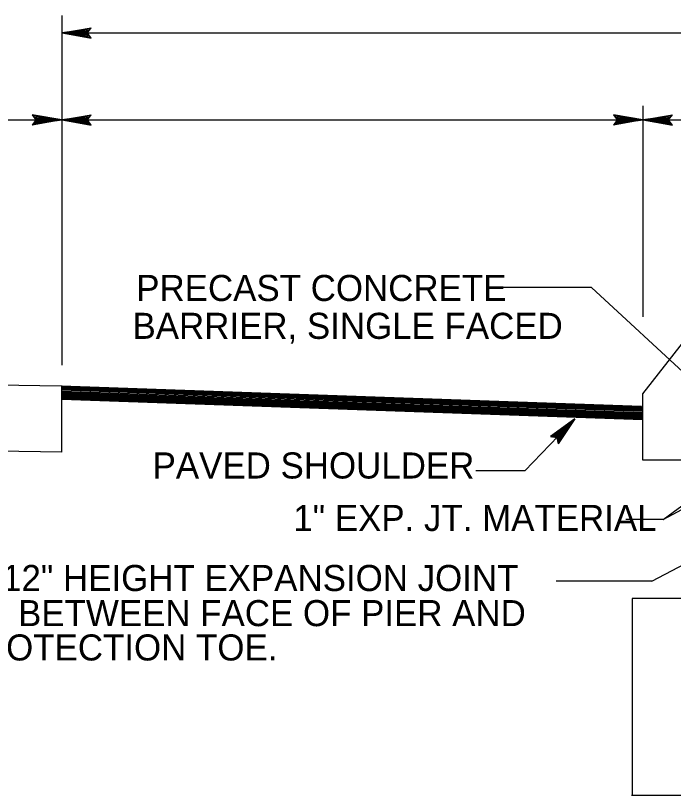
# Model space of a CAD drawing. Extents: x 1553195 to 1553792, y 810516 to 810787.
# Drawn here: x 1553752.03 to 1553765.27, y 810725.5 to 810741.19 of the extents above; entities that cross this region are included whole.
import ezdxf

# ---------------------------------------------------------------- set-up
doc = ezdxf.new("R2010")
doc.units = 0
doc.layers.add('Old_Level_28', color=7, linetype='Continuous')

msp = doc.modelspace()

# ---------------------------------------------------------------- linework, layer by layer
at = {"layer": 'Old_Level_28'}
for p, q in [((1553752.957, 810741.194), (1553752.957, 810734.157)), ((1553752.957, 810740.846), (1553753.552, 810740.948)), ((1553752.957, 810740.846), (1553753.539, 810740.933)), ((1553753.53, 810740.92), (1553752.957, 810740.846)), ((1553752.957, 810740.846), (1553753.519, 810740.904)), ((1553753.477, 810740.846), (1553753.552, 810740.948)), ((1553753.508, 810740.888), (1553752.957, 810740.846)), ((1553752.957, 810740.846), (1553753.497, 810740.875)), ((1553753.486, 810740.859), (1553752.957, 810740.846)), ((1553752.957, 810740.846), (1553767.332, 810740.846)), ((1553752.957, 810740.846), (1553753.552, 810740.739)), ((1553753.539, 810740.754), (1553752.957, 810740.846)), ((1553752.957, 810740.846), (1553753.53, 810740.768)), ((1553753.519, 810740.784), (1553752.957, 810740.846)), ((1553752.957, 810740.846), (1553753.508, 810740.799)), ((1553753.497, 810740.813), (1553752.957, 810740.846)), ((1553752.957, 810740.846), (1553753.486, 810740.828)), ((1553753.477, 810740.846), (1553752.957, 810740.846)), ((1553753.552, 810740.739), (1553753.477, 810740.846)), ((1553764.653, 810739.379), (1553764.653, 810735.13)), ((1553752.957, 810739.095), (1553752.363, 810739.197)), ((1553752.363, 810739.197), (1553752.439, 810739.095)), ((1553752.373, 810739.181), (1553752.957, 810739.095)), ((1553752.957, 810739.095), (1553753.552, 810739.197)), ((1553752.957, 810739.095), (1553753.539, 810739.181)), ((1553753.477, 810739.095), (1553753.552, 810739.197)), ((1553764.653, 810739.095), (1553764.059, 810739.197)), ((1553764.059, 810739.197), (1553764.135, 810739.095)), ((1553764.068, 810739.181), (1553764.653, 810739.095)), ((1553764.653, 810739.095), (1553765.248, 810739.197)), ((1553764.653, 810739.095), (1553765.234, 810739.181)), ((1553765.172, 810739.095), (1553765.248, 810739.197)), ((1553746.957, 810739.095), (1553752.957, 810739.095)), ((1553752.957, 810739.095), (1553752.363, 810738.988)), ((1553752.439, 810739.095), (1553752.363, 810738.988)), ((1553752.957, 810739.095), (1553752.373, 810739.004)), ((1553752.957, 810739.095), (1553752.383, 810739.168)), ((1553752.383, 810739.017), (1553752.957, 810739.095)), ((1553752.397, 810739.152), (1553752.957, 810739.095)), ((1553752.957, 810739.095), (1553752.397, 810739.032)), ((1553752.957, 810739.095), (1553752.406, 810739.137)), ((1553752.406, 810739.048), (1553752.957, 810739.095)), ((1553752.419, 810739.123), (1553752.957, 810739.095)), ((1553752.957, 810739.095), (1553752.419, 810739.061)), ((1553752.957, 810739.095), (1553752.43, 810739.108)), ((1553752.43, 810739.077), (1553752.957, 810739.095)), ((1553752.439, 810739.095), (1553752.957, 810739.095)), ((1553753.53, 810739.168), (1553752.957, 810739.095)), ((1553752.957, 810739.095), (1553753.519, 810739.152)), ((1553753.508, 810739.137), (1553752.957, 810739.095)), ((1553752.957, 810739.095), (1553753.497, 810739.123)), ((1553753.486, 810739.108), (1553752.957, 810739.095)), ((1553752.957, 810739.095), (1553764.653, 810739.095)), ((1553752.957, 810739.095), (1553753.552, 810738.988)), ((1553753.539, 810739.004), (1553752.957, 810739.095)), ((1553752.957, 810739.095), (1553753.53, 810739.017)), ((1553753.519, 810739.032), (1553752.957, 810739.095)), ((1553752.957, 810739.095), (1553753.508, 810739.048)), ((1553753.497, 810739.061), (1553752.957, 810739.095)), ((1553752.957, 810739.095), (1553753.486, 810739.077)), ((1553753.477, 810739.095), (1553752.957, 810739.095)), ((1553753.552, 810738.988), (1553753.477, 810739.095)), ((1553764.653, 810739.095), (1553764.059, 810738.988)), ((1553764.135, 810739.095), (1553764.059, 810738.988)), ((1553764.653, 810739.095), (1553764.068, 810739.004)), ((1553764.653, 810739.095), (1553764.079, 810739.168)), ((1553764.079, 810739.017), (1553764.653, 810739.095)), ((1553764.093, 810739.152), (1553764.653, 810739.095)), ((1553764.653, 810739.095), (1553764.093, 810739.032)), ((1553764.653, 810739.095), (1553764.101, 810739.137)), ((1553764.101, 810739.048), (1553764.653, 810739.095)), ((1553764.115, 810739.123), (1553764.653, 810739.095)), ((1553764.653, 810739.095), (1553764.115, 810739.061)), ((1553764.653, 810739.095), (1553764.126, 810739.108)), ((1553764.126, 810739.077), (1553764.653, 810739.095)), ((1553764.135, 810739.095), (1553764.653, 810739.095)), ((1553765.226, 810739.168), (1553764.653, 810739.095)), ((1553764.653, 810739.095), (1553765.214, 810739.152)), ((1553765.204, 810739.137), (1553764.653, 810739.095)), ((1553764.653, 810739.095), (1553765.192, 810739.123)), ((1553765.181, 810739.108), (1553764.653, 810739.095)), ((1553764.653, 810739.095), (1553765.248, 810738.988)), ((1553765.234, 810739.004), (1553764.653, 810739.095)), ((1553764.653, 810739.095), (1553765.226, 810739.017)), ((1553765.214, 810739.032), (1553764.653, 810739.095)), ((1553764.653, 810739.095), (1553765.204, 810739.048)), ((1553765.192, 810739.061), (1553764.653, 810739.095)), ((1553764.653, 810739.095), (1553765.181, 810739.077)), ((1553765.172, 810739.095), (1553764.653, 810739.095)), ((1553764.653, 810739.095), (1553767.332, 810739.095)), ((1553765.248, 810738.988), (1553765.172, 810739.095)), ((1553763.619, 810735.72), (1553761.693, 810735.72)), ((1553763.619, 810735.72), (1553765.799, 810733.706)), ((1553764.653, 810733.581), (1553765.477, 810734.634)), ((1553746.957, 810733.85), (1553752.95, 810733.739)), ((1553752.95, 810733.739), (1553764.626, 810733.33)), ((1553752.957, 810732.408), (1553752.957, 810733.748)), ((1553752.957, 810733.731), (1553764.65, 810733.321)), ((1553752.957, 810733.717), (1553764.65, 810733.311)), ((1553752.957, 810733.702), (1553764.65, 810733.295)), ((1553752.957, 810733.688), (1553764.65, 810733.281)), ((1553752.957, 810733.672), (1553764.65, 810733.263)), ((1553752.957, 810733.659), (1553764.65, 810733.248)), ((1553752.957, 810733.637), (1553764.65, 810733.23)), ((1553752.957, 810733.617), (1553764.65, 810733.208)), ((1553752.957, 810733.597), (1553764.65, 810733.19)), ((1553752.957, 810733.577), (1553764.65, 810733.168)), ((1553752.957, 810733.561), (1553764.65, 810733.152)), ((1553752.957, 810733.542), (1553764.65, 810733.13)), ((1553752.957, 810733.523), (1553764.65, 810733.115)), ((1553764.653, 810732.243), (1553764.653, 810733.581)), ((1553752.957, 810733.513), (1553764.65, 810733.103)), ((1553752.957, 810733.499), (1553764.65, 810733.09)), ((1553752.957, 810733.488), (1553764.65, 810733.077)), ((1553752.957, 810733.477), (1553764.65, 810733.07)), ((1553752.957, 810733.47), (1553764.65, 810733.061)), ((1553762.276, 810732.033), (1553763.287, 810733.075)), ((1553763.287, 810733.075), (1553762.796, 810732.722)), ((1553762.816, 810732.718), (1553763.287, 810733.075)), ((1553763.287, 810733.075), (1553762.834, 810732.716)), ((1553762.85, 810732.713), (1553763.287, 810733.075)), ((1553763.287, 810733.075), (1553762.87, 810732.713)), ((1553762.887, 810732.709), (1553763.287, 810733.075)), ((1553763.287, 810733.075), (1553762.907, 810732.709)), ((1553762.925, 810732.702), (1553763.287, 810733.075)), ((1553762.927, 810732.684), (1553763.287, 810733.075)), ((1553763.287, 810733.075), (1553762.934, 810732.669)), ((1553762.936, 810732.648), (1553763.287, 810733.075)), ((1553763.287, 810733.075), (1553762.939, 810732.631)), ((1553762.94, 810732.611), (1553763.287, 810733.075)), ((1553763.287, 810733.075), (1553762.947, 810732.575)), ((1553763.287, 810733.075), (1553762.947, 810732.593)), ((1553762.796, 810732.722), (1553762.925, 810732.702)), ((1553762.925, 810732.702), (1553762.947, 810732.575)), ((1553746.968, 810732.522), (1553752.959, 810732.41)), ((1553765.059, 810731.054), (1553767.332, 810732.27)), ((1553766.661, 810732.243), (1553764.653, 810732.243)), ((1553765.059, 810731.054), (1553766.679, 810732.23)), ((1553762.276, 810732.033), (1553761.294, 810732.033)), ((1553765.059, 810731.054), (1553764.308, 810731.054)), ((1553764.837, 810729.808), (1553767.295, 810731.123)), ((1553764.837, 810729.808), (1553762.91, 810729.808)), ((1553767.332, 810729.461), (1553764.435, 810729.461)), ((1553764.435, 810729.461), (1553764.435, 810725.499)), ((1553774.248, 810725.497), (1553764.422, 810725.497))]:
    msp.add_line(p, q, dxfattribs=at)

# ---------------------------------------------------------------- texts
for s, p in [('PRECAST CONCRETE', (1553754.458, 810735.449)), ('BARRIER, SINGLE FACED', (1553754.382, 810734.687)), ('PAVED SHOULDER', (1553754.787, 810731.876)), ('1" EXP. JT. MATERIAL', (1553757.619, 810730.819)), ('MINIMUM 12" HEIGHT EXPANSION JOINT', (1553748.405, 810729.611)), ('MATERIAL BETWEEN FACE OF PIER AND', (1553748.374, 810728.904)), ('SLOPE PROTECTION TOE.', (1553748.328, 810728.213))]:
    msp.add_text(s, height=0.52493, dxfattribs=at).set_placement(p)

doc.saveas('drawing.dxf')
